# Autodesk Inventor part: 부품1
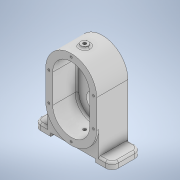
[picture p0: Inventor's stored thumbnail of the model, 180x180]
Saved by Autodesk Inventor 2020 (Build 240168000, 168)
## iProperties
Created: 2021-05
Part Number: 부품1
Material: 일반
Document SubType Name: Modeling
Designer: Owner
Density: 1 g/cm^3
Appearance: 기본값
Author: Owner
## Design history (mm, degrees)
sketch "스케치1"
  geometry: L1 (0, 22.5)-(0, -22.5); L2 (-40, 22.5)-(-40, -22.5); L3 (40, -22.5)-(40, 22.5); A1 r 40 centre (0, 22.5) between (40, 22.5) and (-40, 22.5); A2 r 40 centre (0, -22.5) between (-40, -22.5) and (40, -22.5); 2 further points
  constraints: 8 end point, 4 point on circle, 4 tangent, 2 centre point, 1 coincident, 1 midpoint, 1 parallel, 1 vertical
  dimensions: "d0" = 80 distance between parallel lines of L3 L2; "d1" = 45 distance of L1.end L1.start
extrude "돌출1" new body sketch "스케치1" distance "d2" = 49; taper "d3" = 0 deg
feature "쉘2" dims "d10" = 11
sketch "스케치3"
  geometry: L1 (-40, -22.5)-(-40, 22.5) reference; L2 (-40, 0)-(-40, -59.5); L3 (-40, -59.5)-(-61, -59.5); L4 (-61, -59.5)-(-61, -69.5); L5 (-61, -69.5)-(-35, -69.5); L6 (-35, -69.5)-(-35, -64.5); L7 (-35, -64.5)-(35, -64.5); L8 (35, -64.5)-(35, -69.5); L9 (35, -69.5)-(61, -69.5); L10 (61, -69.5)-(61, -59.5); L11 (61, -59.5)-(40, -59.5); L12 (40, -59.5)-(40, -14.556); L13 (40, 22.5)-(40, -22.5) reference; L14 (0, -104.56)-(0, 90.343) reference; A1 r 40 centre (0, -22.5) between (-40, -22.5) and (40, -22.5) reference; 3 further points
  constraints: 22 end point, 7 perpendicular, 3 point on line, 3 vertical, 1 midpoint, 1 parallel, 3 other
  dimensions: "d11" = 10 distance of L3.end L4.end; "d12" = 122 distance between parallel lines of L10 L4; "d13" = 47 distance from line of L5 L1.start; "d61" = 70 distance between parallel lines of L6 L8; "d62" = 5 distance of L7.end L8.end
extrude "돌출3" join sketch "스케치3" distance "d14" = 46; taper "d15" = 0 deg
sketch "스케치6"
  geometry: L1 (0, 22.5)-(0, -22.5); L2 (-26, 22.5)-(-26, -22.5); L3 (26, -22.5)-(26, 22.5); A1 r 26 centre (0, 22.5) between (26, 22.5) and (-26, 22.5); A2 r 26 centre (0, -22.5) between (-26, -22.5) and (26, -22.5); 2 further points
  constraints: 8 end point, 4 point on circle, 4 tangent, 2 centre point, 1 coincident, 1 midpoint, 1 parallel, 1 vertical
  dimensions: "d19" = 52 distance between parallel lines of L2 L3; "d20" = 45 distance of L1.end L1.start
extrude "돌출4" join sketch "스케치6" distance "d21" = 7; taper "d22" = 0 deg
sketch "스케치7"
  geometry: L1 (0, 22.5)-(0, -22.5); L2 (-26, -7.5)-(-26, -22.5); L3 (26, -22.5)-(26, -7.5); L4 (-26, -7.5)-(26, -7.5); L5 (-61, -69.5)-(-35, -69.5) reference; A1 r 26 centre (0, -22.5) between (-26, -22.5) and (26, -22.5); 2 further points
  constraints: 10 end point, 2 point on circle, 2 tangent, 1 centre point, 1 coincident, 1 midpoint, 1 parallel, 1 perpendicular, 1 vertical, 1 other
  dimensions: "d24" = 30 distance from line of L4 L1.start; "d25" = 52 distance between parallel lines of L3 L2; "d26" = 62 distance between parallel lines of L5 L4
extrude "돌출5" join sketch "스케치7" distance "d27" = 3; taper "d28" = 0 deg
sketch "스케치8"
  geometry: L1 (22.5, 0)-(22.5, 49) reference; L2 (22.5, 32.035)-(22.5, -31.501); L3 (51.5, 11)-(22.5, 11) reference; L4 (36.5, 11)-(36.5, 0); L5 (36.5, 0)-(33.5, 0); L6 (33.5, 0)-(33.5, -4); L7 (33.5, -4)-(36.5, -4); L8 (62.5, 0)-(22.5, 0) reference; L9 (36.5, -4)-(36.5, -7); L10 (22.5, -7)-(48.5, -7) reference; L11 (36.5, -7)-(22.5, -7); 2 further points
  constraints: 14 end point, 3 collinear, 3 point on line, 2 vertical, 1 horizontal, 1 parallel, 1 perpendicular
  dimensions: "d29" = 22 diameter of L6 L1; "d30" = 28 diameter of L9 L2; "d31" = 4 distance of L5.end L6.end; "d32" = 3 distance of L7.end L9.end
revolve "회전1" sketch "스케치8" stored, may be unused: angle "d33" = 90 deg
sketch "스케치9"
  geometry: L1 (-22.5, 11)-(-22.5, 49) reference; L2 (-22.5, 39.78)-(-22.5, -27.628); L3 (22.5, 11)-(-22.5, 11) reference; L4 (-8.5, 11)-(-8.5, 0); L5 (-8.5, 0)-(-12.5, 0); L6 (-12.5, 0)-(-12.5, -4); L7 (-12.5, -4)-(-22.5, -4); 2 further points
  constraints: 10 end point, 3 perpendicular, 3 point on line, 1 collinear, 1 vertical
  dimensions: "d34" = 28 diameter of L4 L2; "d35" = 20 diameter of L6 L2; "d36" = 4 distance of L5.end L6.end; "d37" = 11 distance of L4.start L4.end
revolve "회전2" sketch "스케치9" stored, may be unused: angle "d38" = 90 deg
node "작업 평면2"
sketch "스케치10"
  geometry: L1 (40, 49)-(-40, 49) reference; L2 (0, 28)-(0, 0); C1 r 6 at (0, 28)
  constraints: 2 end point, 1 centre point, 1 vertical
  dimensions: "d41" = 21 distance from line of L2.start L1; "d42" = 12 diameter of C1
extrude "돌출6" join sketch "스케치10" stored distance "d43" = 3; taper "d44" = 0 deg
sketch "스케치11"
  geometry: C1 r 6 at (0, 0) reference; 2 further points
  constraints: 1 coincident
hole "구멍1" sketch "스케치11" at (0, 0) diameter "d45" = 4.917; stored, may be unused: countersink angle "d49" = 90 deg, drill point angle "d51" = 0 deg; dims "d46" = 17, "d47" = 4, "d48" = 2, "d50" = 17.1
sketch "스케치12"
  geometry: L1 (0, 22.5)-(0, -22.5); L2 (-35, 22.5)-(-35, -22.5); L3 (35, -22.5)-(35, 22.5); A1 r 35 centre (0, 22.5) between (35, 22.5) and (-35, 22.5); A2 r 35 centre (0, -22.5) between (-35, -22.5) and (35, -22.5); 8 further points
  constraints: 8 end point, 7 point on circle, 4 coincident, 4 tangent, 2 centre point, 1 midpoint, 1 parallel, 1 point on line, 1 vertical
  dimensions: "d52" = 35 radius of A1; "d53" = 45 distance of L3.start L3.end
hole "구멍2" sketch "스케치12" at (-35, 22.5), (35, -22.5), (-35, -22.5), (0, -57.5), (0, 57.5), (35, 22.5) diameter "d54" = 3.242; stored, may be unused: countersink angle "d58" = 90 deg, drill point angle "d60" = 118 deg; dims "d55" = 8, "d56" = 4, "d57" = 2, "d59" = 10
fillet "모깎기1" dims "d63" = 10
sketch "스케치13"
  geometry: 1 further point
sketch "스케치14"
  geometry: L1 (75, 49)-(-5, 49) reference; L2 (70, 0)-(70, 46) reference; 2 further points
  dimensions: "d64" = 21 distance from line of L1 point (35, 28); "d65" = 35 distance from line of point (35, 28) L2
hole "구멍3" sketch "스케치14" at (35, 28) diameter "d66" = 4.917; stored, may be unused: countersink angle "d70" = 90 deg, drill point angle "d72" = 118 deg; dims "d67" = 12, "d68" = 12, "d69" = 1, "d71" = 17.1
sketch "스케치15" dims "d73" = 40
  geometry: C1 r 11 at (0, 22.5) reference; 3 further points
  constraints: 1 coincident, 1 vertical alignment, 2 other
hole "구멍4" sketch "스케치15" at (0, 42.5) diameter "d74" = 3.242; stored, may be unused: countersink angle "d78" = 90 deg, drill point angle "d80" = 118 deg; dims "d75" = 8, "d76" = 12, "d77" = 1, "d79" = 10
chamfer "모따기1" distance "d84" = 1; stored, may be unused: second distance "d85" = 2, angle "d86" = 45 deg
fillet "모깎기2" dims "d87" = 3
fillet "모깎기3" dims "d88" = 3
fillet "모깎기4" dims "d89" = 3
node "솔리드1"
pattern_circular "원형 패턴1" dims angle "d82" = 360 deg
feature "A9D066F2-1C7D-4E18-AEED-F7BC21143FA4" dims "d54" = 3.242, "d55" = 8, "d56" = 4, "d57" = 2, "d58" = 90 deg, "d59" = 10, "d60" = 118 deg
other parameters: "d40" = 65.5
